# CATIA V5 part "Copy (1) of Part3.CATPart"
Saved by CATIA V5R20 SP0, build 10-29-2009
Part number: Copy (1) of Part3
Bounding box of the stored display mesh (mm): x -0.48 to 0.48, y -41.715 to 0.1, z -0.48 to 0.48
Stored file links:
  C:\Users\scupi\Desktop\Product\Copy (1) of Part3.CATPart

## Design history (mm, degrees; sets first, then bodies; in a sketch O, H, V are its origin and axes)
Body1 (main body)
  DatumCurve1
  Plane1: stored without definition
  Plane2: stored without definition
  Sketch1 on yz-plane, origin (0, 0, 0), H (0, 1, 0), V (0, 0, 1)
    line L1 (-0.1, 0.2) -> (0.1, 0.2)
    line L2 (0.1, 0.2) -> (0.1, 0.4)
    line L3 (-0.1, 0.4) -> (-0.1, 0.2)
    arc A1 centre (0, 0.4) radius 0.1 from (0.1, 0.4) to (-0.1, 0.4) ccw
    point P5 (0, 0.4)
    point P6 (-0.1, 0.4)
    axis line L4 (1.1003, 0) -> (-1.1112, 0)
    point P7 (1.1003, 0)
    distance L2 V = 0.1
    distance L3 L2 = 0.2
    distance H L1 = 0.2
    distance P5 H = 0.4
    radius A1 = 0.1
    horizontal: L1 H, L4 H
    vertical: L2 V, L3 V
    tangency: A1 L3
    coincidence: A1 P6, P7 H
  Shaft1: profile Sketch1, axis Sketch1.L4, angle 360
  Mirror1: of the body so far, about Plane2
